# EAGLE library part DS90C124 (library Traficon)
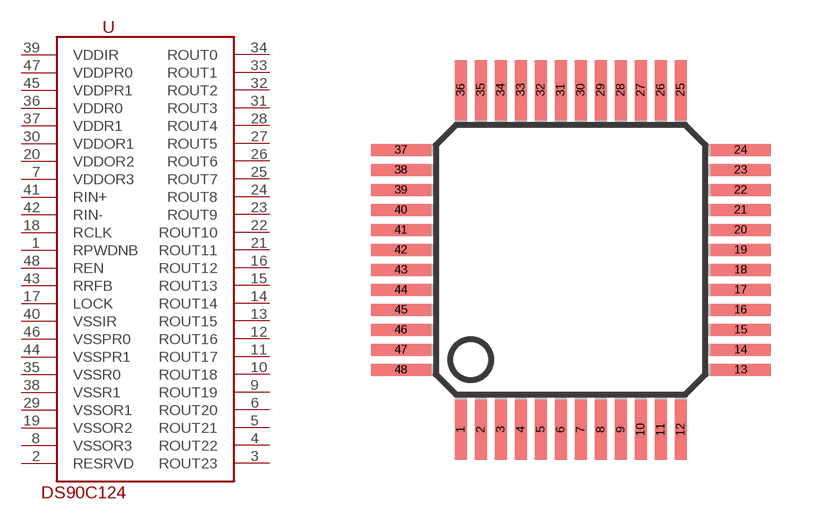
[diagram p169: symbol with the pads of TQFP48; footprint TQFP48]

Designator prefix U

## DS90C124  [TQFP48]
1  RPWDNB  in
2  RESRVD  pas
3  ROUT23  out
4  ROUT22  out
5  ROUT21  out
6  ROUT20  out
7  VDDOR3  sup
8  VSSOR3  sup
9  ROUT19  out
10  ROUT18  out
11  ROUT17  out
12  ROUT16  out
13  ROUT15  out
14  ROUT14  out
15  ROUT13  out
16  ROUT12  out
17  LOCK  out
18  RCLK  out
19  VSSOR2  sup
20  VDDOR2  sup
21  ROUT11  out
22  ROUT10  out
23  ROUT9  out
24  ROUT8  out
25  ROUT7  out
26  ROUT6  out
27  ROUT5  out
28  ROUT4  out
29  VSSOR1  sup
30  VDDOR1  sup
31  ROUT3  out
32  ROUT2  out
33  ROUT1  out
34  ROUT0  out
35  VSSR0  sup
36  VDDR0  sup
37  VDDR1  sup
38  VSSR1  sup
39  VDDIR  sup
40  VSSIR  sup
41  RIN+  in
42  RIN-  in
43  RRFB  in
44  VSSPR1  sup
45  VDDPR1  sup
46  VSSPR0  sup
47  VDDPR0  sup
48  REN  in

## Footprint TQFP48 (pad centres in mm)
Thin Quad Flat Pack
smd 0.3 x 1.5: 1 -2.75,-4.25; 2 -2.25,-4.25; 3 -1.75,-4.25; 4 -1.25,-4.25; 5 -0.75,-4.25; 6 -0.25,-4.25; 7 0.25,-4.25; 8 0.75,-4.25; 9 1.25,-4.25; 10 1.75,-4.25; 11 2.25,-4.25; 12 2.75,-4.25; 25 2.75,4.25; 26 2.25,4.25; 27 1.75,4.25; 28 1.25,4.25; 29 0.75,4.25; 30 0.25,4.25; 31 -0.25,4.25; 32 -0.75,4.25; 33 -1.25,4.25; 34 -1.75,4.25; 35 -2.25,4.25; 36 -2.75,4.25
smd 1.5 x 0.3: 13 4.25,-2.75; 14 4.25,-2.25; 15 4.25,-1.75; 16 4.25,-1.25; 17 4.25,-0.75; 18 4.25,-0.25; 19 4.25,0.25; 20 4.25,0.75; 21 4.25,1.25; 22 4.25,1.75; 23 4.25,2.25; 24 4.25,2.75; 37 -4.25,2.75; 38 -4.25,2.25; 39 -4.25,1.75; 40 -4.25,1.25; 41 -4.25,0.75; 42 -4.25,0.25; 43 -4.25,-0.25; 44 -4.25,-0.75; 45 -4.25,-1.25; 46 -4.25,-1.75; 47 -4.25,-2.25; 48 -4.25,-2.75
